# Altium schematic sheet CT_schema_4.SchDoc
size 287 x 169 mm
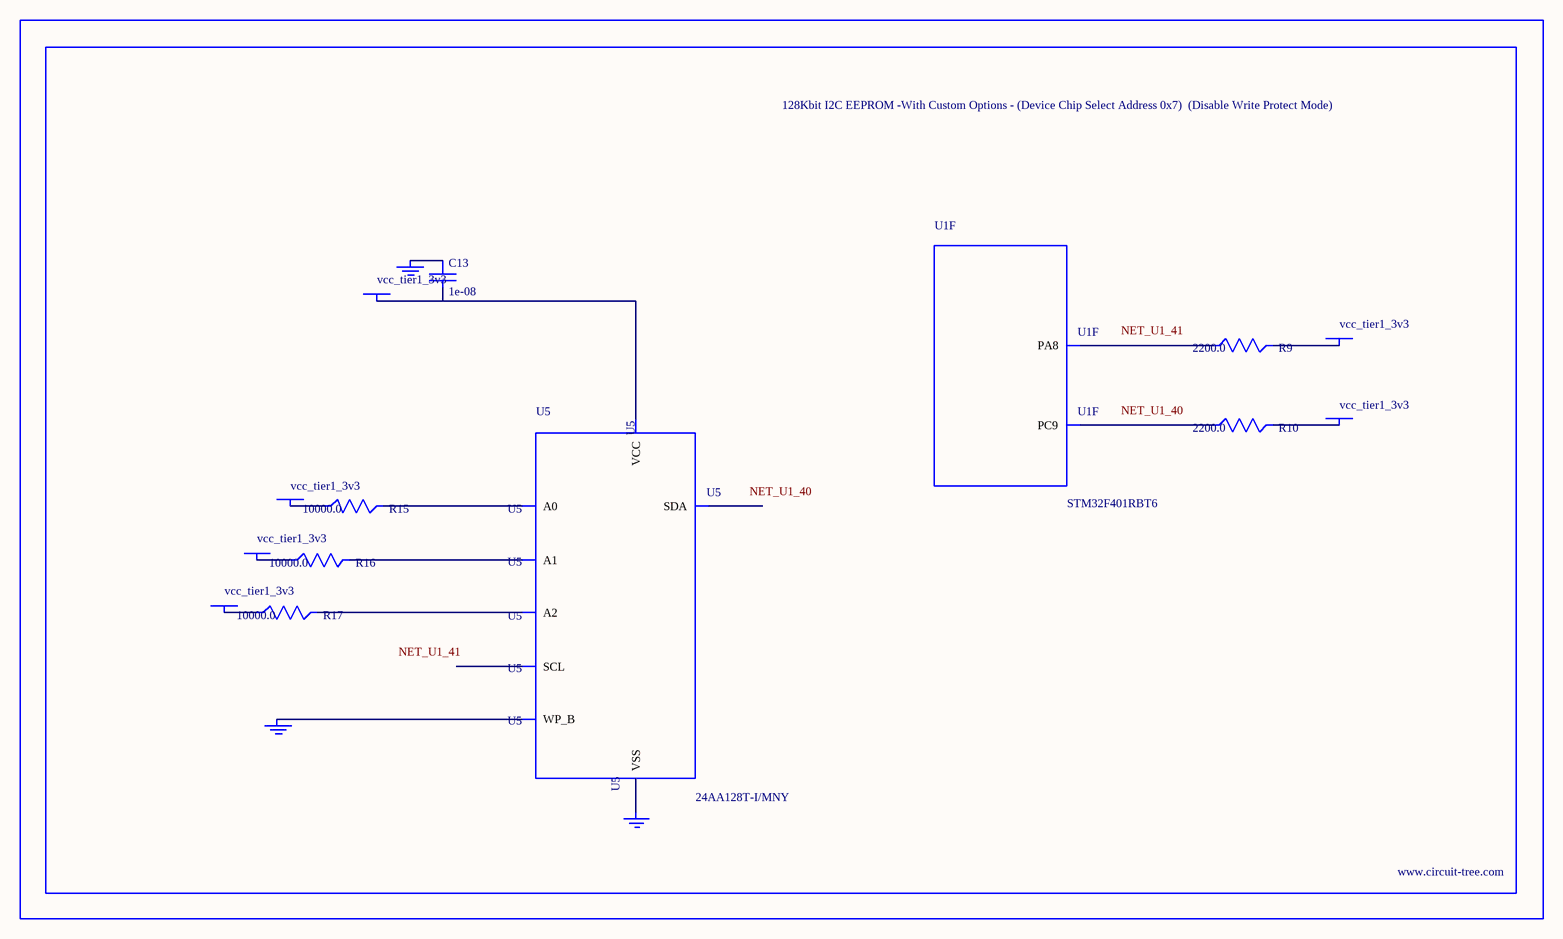
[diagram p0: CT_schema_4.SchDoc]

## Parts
BORDER3  (no value)
C13  1e-08  [C0402]
GND_INSTANCE_3_0  (no value)
GND_INSTANCE_3_1  (no value)
GND_INSTANCE_3_2  (no value)
POWER_INSTANCE_3_0  vcc_tier1_3v3
POWER_INSTANCE_3_1  vcc_tier1_3v3
POWER_INSTANCE_3_2  vcc_tier1_3v3
POWER_INSTANCE_3_3  vcc_tier1_3v3
POWER_INSTANCE_3_4  vcc_tier1_3v3
POWER_INSTANCE_3_5  vcc_tier1_3v3
R9  2200.0  [R0603]
R10  2200.0  [R0603]
R15  10000.0  [R0603]
R16  10000.0  [R0603]
R17  10000.0  [R0603]
U1  STM32F401RBT6  [LQFP64]  (part F of 7)
U5  24AA128T-I/MNY  [TDFN-8/6MM]

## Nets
NetC13_1: C13.1 GND_INSTANCE_3_1.0(GND)
NetC13_2: C13.2 POWER_INSTANCE_3_3.0(PWR) U5.8(VCC)
NetGND_INSTANCE_3_0_0: GND_INSTANCE_3_0.0(GND) U5.7(WP_B)
NetGND_INSTANCE_3_2_0: GND_INSTANCE_3_2.0(GND) U5.4(VSS)
NetPOWER_INSTANCE_3_0_0: POWER_INSTANCE_3_0.0(PWR) R15.1
NetPOWER_INSTANCE_3_1_0: POWER_INSTANCE_3_1.0(PWR) R16.1
NetPOWER_INSTANCE_3_2_0: POWER_INSTANCE_3_2.0(PWR) R17.1
NetPOWER_INSTANCE_3_4_0: POWER_INSTANCE_3_4.0(PWR) R10.2
NetPOWER_INSTANCE_3_5_0: POWER_INSTANCE_3_5.0(PWR) R9.2
NetR9_1: R9.1 U1.41(PA8)
NetR10_1: R10.1 U1.40(PC9)
NetR15_2: R15.2 U5.1(A0)
NetR16_2: R16.2 U5.2(A1)
NetR17_2: R17.2 U5.3(A2)

Not connected (* = marked no-connect by the designer): U5 5(SDA) 6(SCL)

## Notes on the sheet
- Labels drawn without touching a wire or pin: NET_U1_40, NET_U1_41

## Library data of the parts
BORDER3 = BORDER_PAGE3
C13 = C0402C103K3RAC
GND_INSTANCE_3_0-GND_INSTANCE_3_2 = GND
POWER_INSTANCE_3_0-POWER_INSTANCE_3_5 = PWR
R9 R10 = RC0603JR-072K2L
R15-R17 = RC0603JR-0710KL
